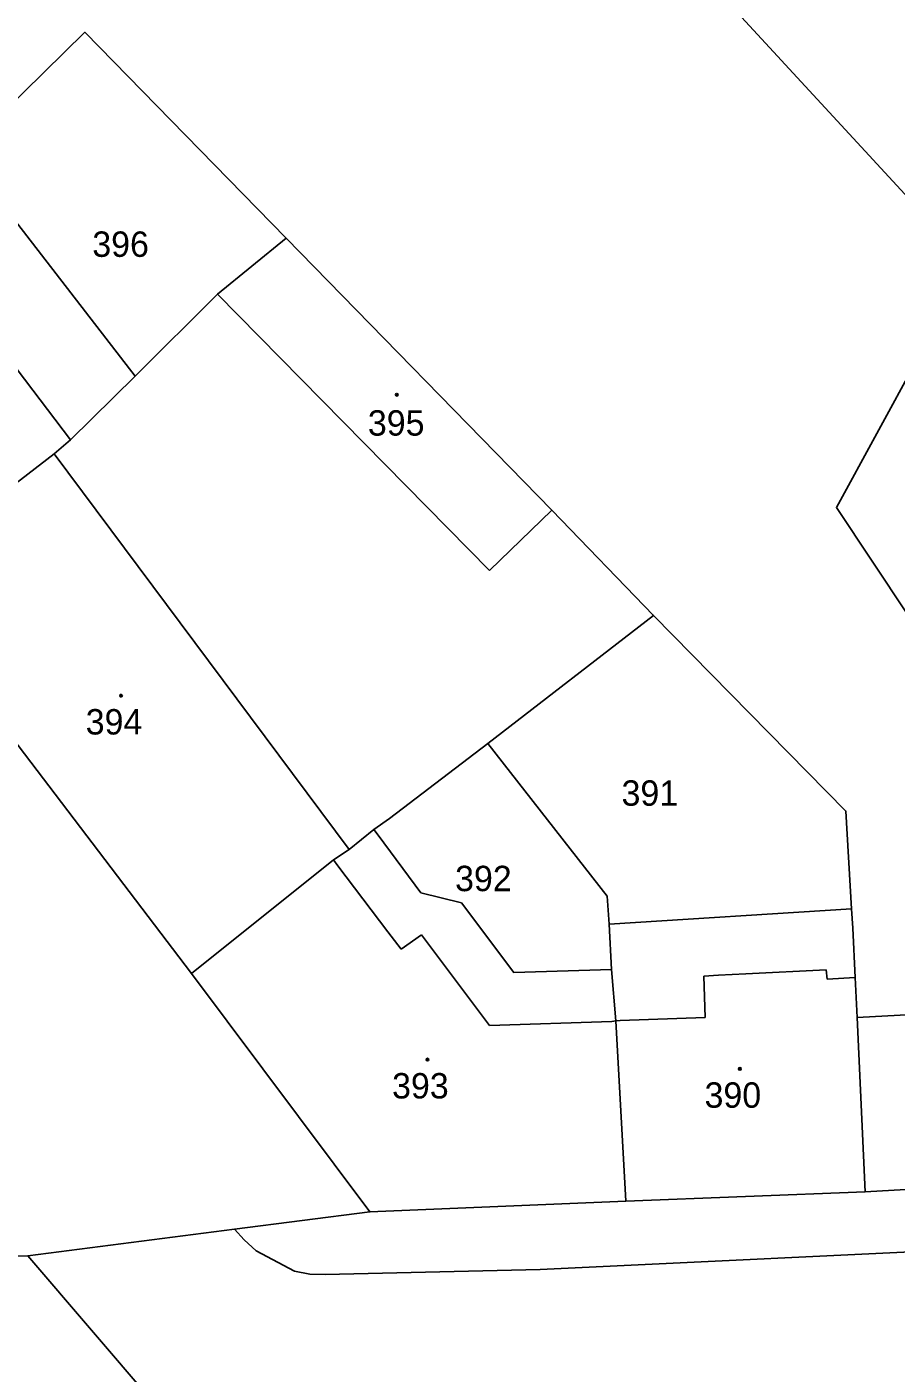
# Model space of a CAD drawing. Extents: x -598934 to -598196, y -1162208 to -1161502.
# Drawn here: x -598884.8 to -598826.6, y -1162016.6 to -1161926.4 of the extents above; entities that cross this region are included whole.
import ezdxf

# ---------------------------------------------------------------- set-up
doc = ezdxf.new("R2010")
doc.units = 0
for name, color, linetype in [('KN_CAR_KR', 7, 'Continuous'), ('KN_KULTURY', 7, 'Continuous'), ('KN_PARC_CIS_POZ', 7, 'Continuous'), ('KN_PARC_CIS_STAV', 7, 'Continuous'), ('KN_PARC_PLOCHA', 7, 'Continuous'), ('parcely_l', 7, 'Continuous')]:
    doc.layers.add(name, color=color, linetype=linetype)

msp = doc.modelspace()

# ---------------------------------------------------------------- linework, layer by layer
at = {"layer": 'KN_CAR_KR'}
for points in [[(-598853.78, -1161962.85), (-598872.02, -1161944.33)], [(-598885.42, -1161949.38), (-598881.85, -1161954.09)], [(-598849.62, -1161958.8), (-598853.78, -1161962.85)], [(-598864.24, -1161982.22), (-598863.95, -1161982.62)], [(-598863.95, -1161982.62), (-598860.6, -1161987.04)], [(-598860.6, -1161987.04), (-598859.7, -1161988.19)], [(-598859.7, -1161988.19), (-598858.35, -1161987.23)], [(-598858.35, -1161987.23), (-598853.8, -1161993.3)], [(-598838.45, -1161989.94), (-598836.62, -1161989.85)], [(-598836.62, -1161989.85), (-598831.24, -1161989.57)], [(-598831.24, -1161989.57), (-598831.18, -1161990.2)], [(-598839.44, -1161989.99), (-598838.45, -1161989.94)], [(-598839.34, -1161992.77), (-598839.44, -1161989.99)], [(-598831.18, -1161990.2), (-598829.29, -1161990.1)], [(-598853.8, -1161993.3), (-598845.59, -1161993.04)], [(-598845.59, -1161993.04), (-598845.34, -1161993)], [(-598845.34, -1161993), (-598845.05, -1161992.98)], [(-598845.05, -1161992.98), (-598839.34, -1161992.77)]]:
    msp.add_lwpolyline(points, dxfattribs=at)
at = {"layer": 'KN_KULTURY'}
for centre, radius in [((-598860, -1161951.07), 0.09), ((-598860, -1161951.07), 0.0398), ((-598878.47, -1161971.22), 0.09), ((-598878.47, -1161971.22), 0.0398), ((-598857.95, -1161995.59), 0.09), ((-598857.95, -1161995.59), 0.0398), ((-598837.02, -1161996.21), 0.09), ((-598837.02, -1161996.21), 0.0398)]:
    msp.add_circle(centre, radius, dxfattribs=at)
at = {"layer": 'KN_PARC_PLOCHA'}
for points in [[(-598824.89, -1161938.81), (-598887.13, -1161871.41), (-598887.58, -1161871.09), (-598888.33, -1161870.94), (-598888.87, -1161871.08), (-598889.28, -1161871.31), (-598893.09, -1161874.87), (-598906.75, -1161860.04)], [(-598906.75, -1161860.04), (-598893.09, -1161874.87), (-598889.28, -1161871.31), (-598888.87, -1161871.08), (-598888.33, -1161870.94), (-598887.58, -1161871.09), (-598887.13, -1161871.41), (-598824.89, -1161938.81)], [(-598820.93, -1161992.32), (-598829.17, -1161992.77), (-598829.29, -1161990.1), (-598829.45, -1161986.79), (-598829.55, -1161985.5), (-598829.92, -1161978.95), (-598842.8, -1161965.85), (-598849.62, -1161958.8), (-598867.42, -1161940.58), (-598880.89, -1161926.8), (-598889.11, -1161934.86), (-598893.33, -1161938.99), (-598896.07, -1161941.68), (-598900.57, -1161935.66), (-598897.41, -1161933.11), (-598907.94, -1161919.22), (-598928.61, -1161891.58), (-598931.22, -1161882.34), (-598932.017, -1161880.677), (-598932.017, -1161860.81)], [(-598816.21, -1161980.17), (-598830.55, -1161958.62), (-598825.15, -1161948.72)], [(-598825.15, -1161948.72), (-598830.55, -1161958.62), (-598816.21, -1161980.17)], [(-598884.94, -1161975.11), (-598873.75, -1161989.83), (-598861.8, -1162005.79), (-598870.88, -1162006.95), (-598884.71, -1162008.72), (-598896.69, -1162008.84)], [(-598819.47, -1162008.16), (-598850.4, -1162009.63), (-598864.79, -1162009.98), (-598865.83, -1162009.95), (-598866.85, -1162009.75), (-598869.42, -1162008.38), (-598870.22, -1162007.65), (-598870.88, -1162006.95), (-598861.8, -1162005.79), (-598844.65, -1162005.06), (-598828.63, -1162004.44), (-598814.58, -1162003.63)], [(-598876.32, -1162018.53), (-598884.71, -1162008.72), (-598870.88, -1162006.95), (-598870.22, -1162007.65), (-598869.42, -1162008.38), (-598866.85, -1162009.75), (-598865.83, -1162009.95), (-598864.79, -1162009.98), (-598850.4, -1162009.63), (-598819.47, -1162008.16)]]:
    msp.add_lwpolyline(points, dxfattribs=at)
for points in [[(-598867.42, -1161940.58), (-598872.02, -1161944.33), (-598877.53, -1161949.83), (-598889.11, -1161934.86), (-598880.89, -1161926.8)], [(-598877.53, -1161949.83), (-598881.85, -1161954.09), (-598882.96, -1161955.02), (-598893.84, -1161963.41), (-598904.02, -1161949.98), (-598896.07, -1161941.68), (-598893.33, -1161938.99), (-598889.11, -1161934.86)], [(-598842.8, -1161965.85), (-598853.91, -1161974.42), (-598860.49, -1161979.44), (-598861.53, -1161980.19), (-598863.18, -1161981.51), (-598882.96, -1161955.02), (-598881.85, -1161954.09), (-598877.53, -1161949.83), (-598872.02, -1161944.33), (-598867.42, -1161940.58), (-598849.62, -1161958.8)], [(-598863.18, -1161981.51), (-598864.24, -1161982.22), (-598873.75, -1161989.83), (-598884.94, -1161975.11), (-598893.84, -1161963.41), (-598882.96, -1161955.02)], [(-598829.55, -1161985.5), (-598845.77, -1161986.52), (-598845.9, -1161984.64), (-598853.91, -1161974.42), (-598842.8, -1161965.85), (-598829.92, -1161978.95)], [(-598845.77, -1161986.52), (-598845.62, -1161989.55), (-598852.17, -1161989.75), (-598855.67, -1161985.1), (-598858.38, -1161984.43), (-598861.24, -1161980.55), (-598861.53, -1161980.19), (-598860.49, -1161979.44), (-598853.91, -1161974.42), (-598845.9, -1161984.64)], [(-598845.62, -1161989.55), (-598845.34, -1161993), (-598844.65, -1162005.06), (-598861.8, -1162005.79), (-598873.75, -1161989.83), (-598864.24, -1161982.22), (-598863.18, -1161981.51), (-598861.53, -1161980.19), (-598861.24, -1161980.55), (-598858.38, -1161984.43), (-598855.67, -1161985.1), (-598852.17, -1161989.75)], [(-598829.17, -1161992.77), (-598828.63, -1162004.44), (-598844.65, -1162005.06), (-598845.34, -1161993), (-598845.62, -1161989.55), (-598845.77, -1161986.52), (-598829.55, -1161985.5), (-598829.45, -1161986.79), (-598829.29, -1161990.1)], [(-598807.43, -1161993.63), (-598809.85, -1161997.02), (-598812.6, -1162000.8), (-598814.58, -1162003.63), (-598828.63, -1162004.44), (-598829.17, -1161992.77), (-598820.93, -1161992.32), (-598816.98, -1161986.74)], [(-598912.15, -1162007.46), (-598902.86, -1162008.29), (-598896.69, -1162008.84), (-598884.71, -1162008.72), (-598876.32, -1162018.53), (-598873.13, -1162022.24), (-598891.39, -1162023.04), (-598909.46, -1162023.88), (-598914.65, -1162024.03), (-598932.017, -1162024.888), (-598932.017, -1162008.017), (-598917.65, -1162007.34), (-598917.64, -1162007.83)]]:
    msp.add_lwpolyline(points, close=True, dxfattribs=at)
at = {"layer": 'parcely_l'}
for points in [[(-598906.75, -1161860.04), (-598893.09, -1161874.87), (-598889.28, -1161871.31), (-598888.87, -1161871.08), (-598888.33, -1161870.94), (-598887.58, -1161871.09), (-598887.13, -1161871.41), (-598824.89, -1161938.81), (-598823.93, -1161940.34), (-598823.36, -1161942.42), (-598823.35, -1161943.59), (-598823.52, -1161944.84), (-598823.81, -1161945.75), (-598825.15, -1161948.72), (-598830.55, -1161958.62), (-598816.21, -1161980.17), (-598815.09, -1161978.66)], [(-598889.11, -1161934.86), (-598880.89, -1161926.8), (-598867.42, -1161940.58)], [(-598877.53, -1161949.83), (-598889.11, -1161934.86)], [(-598867.42, -1161940.58), (-598872.02, -1161944.33), (-598877.53, -1161949.83)], [(-598867.42, -1161940.58), (-598849.62, -1161958.8), (-598842.8, -1161965.85)], [(-598882.96, -1161955.02), (-598881.85, -1161954.09), (-598877.53, -1161949.83)], [(-598882.96, -1161955.02), (-598893.84, -1161963.41)], [(-598863.18, -1161981.51), (-598882.96, -1161955.02)], [(-598853.91, -1161974.42), (-598842.8, -1161965.85)], [(-598842.8, -1161965.85), (-598829.92, -1161978.95), (-598829.55, -1161985.5)], [(-598853.91, -1161974.42), (-598860.49, -1161979.44), (-598861.53, -1161980.19)], [(-598845.77, -1161986.52), (-598845.9, -1161984.64), (-598853.91, -1161974.42)], [(-598873.75, -1161989.83), (-598884.94, -1161975.11)], [(-598861.53, -1161980.19), (-598863.18, -1161981.51)], [(-598861.53, -1161980.19), (-598861.24, -1161980.55), (-598858.38, -1161984.43), (-598855.67, -1161985.1), (-598852.17, -1161989.75), (-598845.62, -1161989.55)], [(-598873.75, -1161989.83), (-598864.24, -1161982.22), (-598863.18, -1161981.51)], [(-598829.55, -1161985.5), (-598845.77, -1161986.52)], [(-598829.55, -1161985.5), (-598829.45, -1161986.79), (-598829.29, -1161990.1), (-598829.17, -1161992.77)], [(-598845.62, -1161989.55), (-598845.77, -1161986.52)], [(-598816.98, -1161986.74), (-598820.93, -1161992.32), (-598829.17, -1161992.77)], [(-598861.8, -1162005.79), (-598873.75, -1161989.83)], [(-598845.62, -1161989.55), (-598845.34, -1161993), (-598844.65, -1162005.06)], [(-598829.17, -1161992.77), (-598828.63, -1162004.44)], [(-598870.88, -1162006.95), (-598870.22, -1162007.65), (-598869.42, -1162008.38), (-598866.85, -1162009.75), (-598865.83, -1162009.95), (-598864.79, -1162009.98), (-598850.4, -1162009.63), (-598819.47, -1162008.16), (-598808.67, -1162007.3), (-598804.24, -1162006.6), (-598799.16, -1162004.93), (-598794.79, -1162002.85)], [(-598828.63, -1162004.44), (-598814.58, -1162003.63)], [(-598844.65, -1162005.06), (-598861.8, -1162005.79)], [(-598828.63, -1162004.44), (-598844.65, -1162005.06)], [(-598870.88, -1162006.95), (-598861.8, -1162005.79)], [(-598884.71, -1162008.72), (-598870.88, -1162006.95)], [(-598896.69, -1162008.84), (-598884.71, -1162008.72)], [(-598873.13, -1162022.24), (-598876.32, -1162018.53), (-598884.71, -1162008.72)]]:
    msp.add_lwpolyline(points, dxfattribs=at)

# ---------------------------------------------------------------- texts
at = {"layer": 'KN_PARC_CIS_POZ'}
for s, p in [('396', (-598880.397, -1161941.84)), ('391', (-598844.947, -1161978.59)), ('392', (-598856.097, -1161984.31))]:
    msp.add_text(s, height=1.7, dxfattribs=at).set_placement(p)
at = {"layer": 'KN_PARC_CIS_STAV'}
for s, p in [('395', (-598861.937, -1161953.81)), ('394', (-598880.837, -1161973.82)), ('393', (-598860.317, -1161998.19)), ('390', (-598839.387, -1161998.81))]:
    msp.add_text(s, height=1.7, dxfattribs=at).set_placement(p)

doc.saveas('drawing.dxf')
